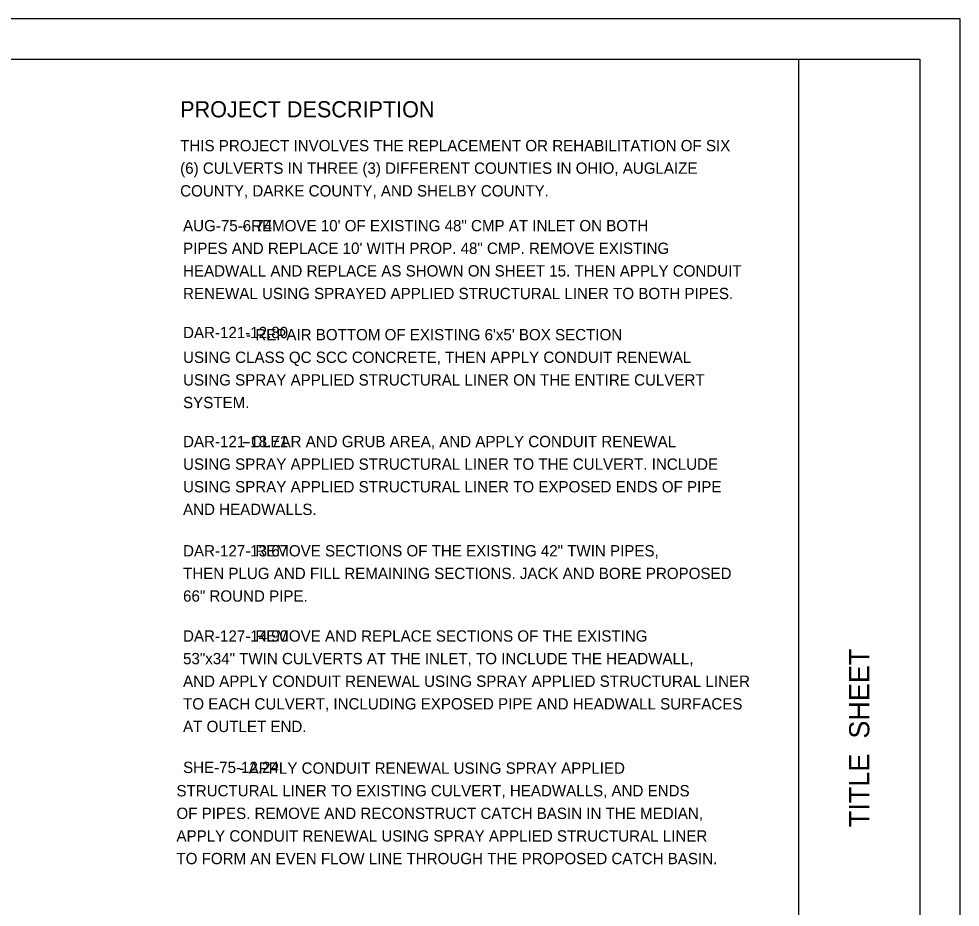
# Model space of a CAD drawing. Extents: x 0 to 34, y 0 to 22.
# Drawn here: x 22.34 to 34, y 11 to 22 of the extents above; entities that cross this region are included whole.
import ezdxf

# ---------------------------------------------------------------- set-up
doc = ezdxf.new("R2010")
doc.units = 0
for name, color, linetype in [('SH_Border', 7, 'Continuous'), ('SH_Cut_Line', 7, 'Continuous'), ('SH_Data', 7, 'Continuous'), ('SH_Text', 7, 'Continuous')]:
    doc.layers.add(name, color=color, linetype=linetype)

msp = doc.modelspace()

# ---------------------------------------------------------------- linework, layer by layer
at = {"layer": 'SH_Border'}
msp.add_line((32, 0.5), (32, 21.5), dxfattribs=at)
msp.add_lwpolyline([(1.5, 21.5), (33.5, 21.5), (33.5, 0.5), (1.5, 0.5)], close=True, dxfattribs=at)
at = {"layer": 'SH_Cut_Line'}
msp.add_lwpolyline([(0, 0), (34, 0), (34, 22), (0, 22)], close=True, dxfattribs=at)

# ---------------------------------------------------------------- texts
at = {"layer": 'SH_Data'}
msp.add_text('TITLE  SHEET', height=0.25, rotation=90, dxfattribs=at).set_placement((32.875, 11.991))
at = {"layer": 'SH_Text'}
for s, height, p in [('PROJECT DESCRIPTION', 0.2, (24.339, 20.78)), ('THIS PROJECT INVOLVES THE REPLACEMENT OR REHABILITATION OF SIX ', 0.14, (24.339, 20.36)), ('(6) CULVERTS IN THREE (3) DIFFERENT COUNTIES IN OHIO, AUGLAIZE ', 0.14, (24.339, 20.081)), ('COUNTY, DARKE COUNTY, AND SHELBY COUNTY.', 0.14, (24.339, 19.8)), ('AUG-75-6.74', 0.14, (24.375, 19.369)), ('              - REMOVE 10\' OF EXISTING 48" CMP AT INLET ON BOTH ', 0.14, (24.375, 19.369)), ('PIPES AND REPLACE 10\' WITH PROP. 48" CMP. REMOVE EXISTING ', 0.14, (24.375, 19.089)), ('HEADWALL AND REPLACE AS SHOWN ON SHEET 15. THEN APPLY CONDUIT', 0.14, (24.375, 18.809)), ('RENEWAL USING SPRAYED APPLIED STRUCTURAL LINER TO BOTH PIPES.', 0.14, (24.375, 18.529)), ('DAR-121-12.80', 0.14, (24.375, 18.046)), ("               - REPAIR BOTTOM OF EXISTING 6'x5' BOX SECTION ", 0.14, (24.375, 18.019)), ('USING CLASS QC SCC CONCRETE, THEN APPLY CONDUIT RENEWAL ', 0.14, (24.375, 17.739)), ('USING SPRAY APPLIED STRUCTURAL LINER ON THE ENTIRE CULVERT', 0.14, (24.375, 17.459)), ('SYSTEM.', 0.14, (24.375, 17.179)), ('DAR-121-18.71', 0.14, (24.375, 16.696)), ('              - CLEAR AND GRUB AREA, AND APPLY CONDUIT RENEWAL', 0.14, (24.375, 16.696)), ('USING SPRAY APPLIED STRUCTURAL LINER TO THE CULVERT. INCLUDE  ', 0.14, (24.375, 16.416)), ('USING SPRAY APPLIED STRUCTURAL LINER TO EXPOSED ENDS OF PIPE ', 0.14, (24.375, 16.136)), ('AND HEADWALLS.', 0.14, (24.375, 15.856)), ('DAR-127-13.67', 0.14, (24.375, 15.343)), ('               - REMOVE SECTIONS OF THE EXISTING 42" TWIN PIPES,', 0.14, (24.375, 15.343)), ('THEN PLUG AND FILL REMAINING SECTIONS. JACK AND BORE PROPOSED', 0.14, (24.375, 15.063)), ('66" ROUND PIPE.', 0.14, (24.375, 14.783)), ('DAR-127-14.90', 0.14, (24.375, 14.288)), ('               - REMOVE AND REPLACE SECTIONS OF THE EXISTING ', 0.14, (24.375, 14.288)), ('53"x34" TWIN CULVERTS AT THE INLET, TO INCLUDE THE HEADWALL,  ', 0.14, (24.375, 14.008)), ('AND APPLY CONDUIT RENEWAL USING SPRAY APPLIED STRUCTURAL LINER   ', 0.14, (24.375, 13.728)), ('TO EACH CULVERT, INCLUDING EXPOSED PIPE AND HEADWALL SURFACES  ', 0.14, (24.375, 13.448)), ('AT OUTLET END.', 0.14, (24.375, 13.168)), ('SHE-75-12.24', 0.14, (24.375, 12.661)), ('               - APPLY CONDUIT RENEWAL USING SPRAY APPLIED ', 0.14, (24.293, 12.652)), ('STRUCTURAL LINER TO EXISTING CULVERT, HEADWALLS, AND ENDS ', 0.14, (24.293, 12.372)), ('OF PIPES. REMOVE AND RECONSTRUCT CATCH BASIN IN THE MEDIAN, ', 0.14, (24.293, 12.092)), ('APPLY CONDUIT RENEWAL USING SPRAY APPLIED STRUCTURAL LINER ', 0.14, (24.293, 11.812)), ('TO FORM AN EVEN FLOW LINE THROUGH THE PROPOSED CATCH BASIN.', 0.14, (24.293, 11.532))]:
    msp.add_text(s, height=height, dxfattribs=at).set_placement(p)

doc.saveas('drawing.dxf')
